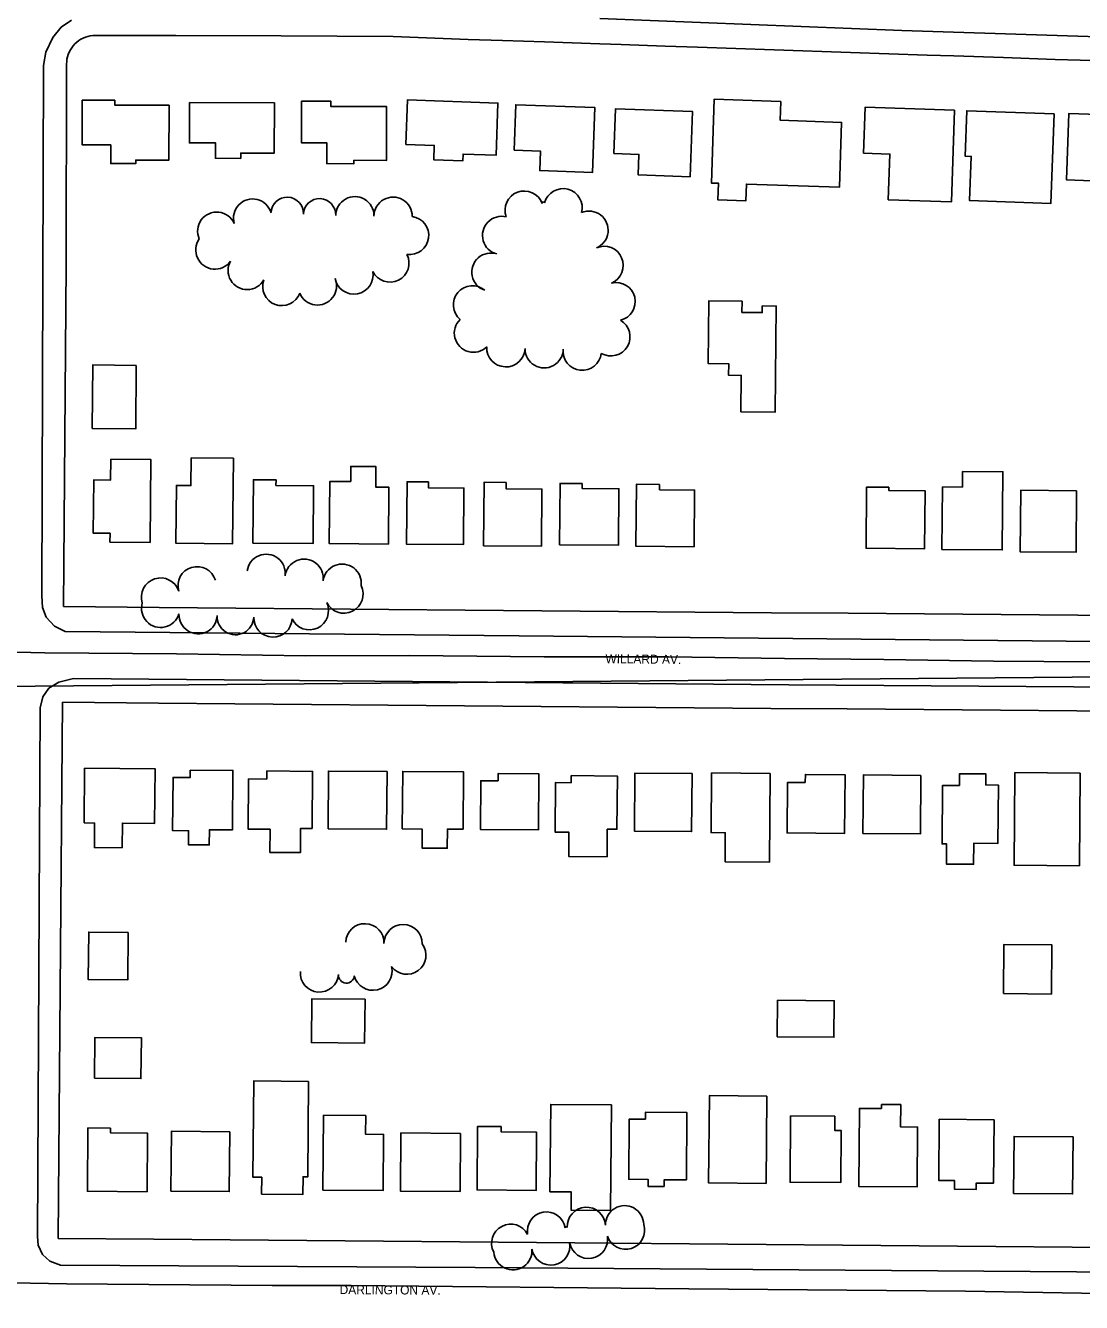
# Model space of a CAD drawing. Extents: x -2233 to 187241, y 4582 to 150524.
# Drawn here: x 113336 to 113887, y 57751 to 58418 of the extents above; entities that cross this region are included whole.
import ezdxf

# ---------------------------------------------------------------- set-up
doc = ezdxf.new("R2010")
doc.units = 0
for name, color, linetype in [('BLDG', 7, 'Continuous'), ('GE_X_CL_2000', 7, 'Continuous'), ('GRID', 7, 'Continuous'), ('ROAD', 7, 'Continuous'), ('ROAD-NAME', 7, 'Continuous'), ('RW_X_Fee_RW', 7, 'Continuous'), ('TREES', 7, 'Continuous')]:
    doc.layers.add(name, color=color, linetype=linetype)

msp = doc.modelspace()

# ---------------------------------------------------------------- linework, layer by layer
at = {"layer": 'BLDG'}
for points in [[(113380.26, 58355.66), (113380.24, 58345.86), (113393.23, 58345.82), (113393.23, 58347.68), (113410.63, 58347.64), (113410.7, 58376.38), (113382.31, 58376.44), (113382.31, 58378.93), (113365.28, 58378.98), (113365.22, 58355.69)], [(113421.35, 58377.7), (113465.72, 58377.59), (113465.66, 58351.32), (113448.15, 58351.37), (113448.14, 58348.58), (113434.94, 58348.61), (113434.96, 58356.64), (113421.29, 58356.67)], [(113479.89, 58378.49), (113495.28, 58378.45), (113495.27, 58375.67), (113524.37, 58375.6), (113524.31, 58347.52), (113507.29, 58347.56), (113507.28, 58345.77), (113493.07, 58345.81), (113493.1, 58356.71), (113479.84, 58356.74)], [(113534.39, 58355.88), (113549.28, 58355.36), (113549.02, 58347.86), (113564.2, 58347.33), (113564.33, 58350.8), (113581.57, 58350.2), (113582.52, 58377.49), (113535.19, 58379.15)], [(113730.4, 58378.37), (113730.05, 58368.51), (113762.14, 58367.39), (113760.96, 58333.49), (113712.34, 58335.18), (113712.03, 58326.32), (113697.52, 58326.83), (113697.82, 58335.54), (113694.05, 58335.67), (113695.58, 58379.59)], [(113591.02, 58352.87), (113604.75, 58352.38), (113604.4, 58342.23), (113631.96, 58341.27), (113633.14, 58375.19), (113591.86, 58376.64)], [(113643.16, 58351.14), (113656.2, 58350.68), (113655.82, 58339.92), (113682.95, 58338.98), (113684.14, 58373.09), (113643.98, 58374.5)], [(113821.14, 58373.76), (113819.47, 58325.8), (113786.5, 58326.95), (113787.34, 58350.85), (113773.59, 58351.33), (113774.43, 58375.4)], [(113873.12, 58371.91), (113871.49, 58324.99), (113829.01, 58326.47), (113829.82, 58349.56), (113826.72, 58349.67), (113827.55, 58373.5)], [(113927.27, 58370.42), (113925.58, 58321.86), (113892.3, 58323.03), (113892.79, 58336.86), (113879.71, 58337.31), (113880.92, 58372.04)], [(113710.11, 58273.89), (113710.06, 58268.1), (113720.61, 58268), (113720.64, 58271.43), (113727.95, 58271.37), (113727.47, 58216), (113709.52, 58216.15), (113709.69, 58235.14), (113703.08, 58235.19), (113703.12, 58241.2), (113692.39, 58241.3), (113692.68, 58274.04)], [(113393.56, 58240.39), (113393.28, 58207.21), (113370.53, 58207.42), (113370.81, 58240.58)], [(113380.21, 58191.35), (113380.12, 58180.44), (113371.29, 58180.51), (113371.05, 58152.68), (113379.85, 58152.6), (113379.81, 58148), (113400.78, 58147.83), (113401.15, 58191.17)], [(113422.21, 58192.06), (113422.09, 58177.53), (113414.49, 58177.6), (113414.22, 58147.4), (113443.91, 58147.15), (113444.29, 58191.87)], [(113505.59, 58179.64), (113505.65, 58187.58), (113518.76, 58187.47), (113518.67, 58176.77), (113525.52, 58176.71), (113525.27, 58146.96), (113494.42, 58147.22), (113494.7, 58179.74)], [(113825.34, 58184.97), (113825.27, 58176.74), (113814.85, 58176.83), (113814.57, 58144.16), (113846.03, 58143.89), (113846.38, 58184.8)], [(113466.54, 58177.62), (113466.56, 58180.48), (113454.77, 58180.59), (113454.49, 58147.48), (113485.93, 58147.21), (113486.19, 58177.46)], [(113546.26, 58179.45), (113546.23, 58176.39), (113564.71, 58176.23), (113564.46, 58146.74), (113534.74, 58146.99), (113535.02, 58179.55)], [(113586.78, 58179.2), (113586.75, 58175.89), (113605.48, 58175.73), (113605.22, 58145.86), (113575.01, 58146.12), (113575.29, 58179.3)], [(113626.61, 58178.56), (113626.59, 58176.02), (113645.74, 58175.86), (113645.49, 58146.36), (113614.72, 58146.62), (113614.99, 58178.66)], [(113666.99, 58178.12), (113666.97, 58175.34), (113685.32, 58175.18), (113685.07, 58145.57), (113654.6, 58145.82), (113654.88, 58178.23)], [(113786.72, 58176.65), (113786.71, 58175.05), (113805.76, 58174.88), (113805.49, 58144.58), (113774.9, 58144.84), (113775.17, 58176.75)], [(113884.91, 58174.87), (113884.64, 58142.73), (113855.41, 58142.98), (113855.69, 58175.12)], [(113366.27, 58001.23), (113371.74, 58001.18), (113371.63, 57988.37), (113386.17, 57988.24), (113386.28, 58001.12), (113403.14, 58000.97), (113403.38, 58029.53), (113366.51, 58029.83)], [(113421.71, 58028.84), (113421.67, 58024.92), (113412.79, 58025.01), (113412.55, 57997.24), (113420.88, 57997.18), (113420.82, 57989.81), (113431.65, 57989.71), (113431.72, 57997.71), (113443.81, 57997.61), (113444.08, 58028.65)], [(113461.78, 58028.41), (113461.74, 58024.12), (113452.19, 58024.21), (113451.97, 57998.05), (113463.5, 57997.95), (113463.39, 57985.87), (113479.3, 57985.73), (113479.41, 57998.39), (113485.39, 57998.33), (113485.65, 58028.2)], [(113493.74, 57998.23), (113524.35, 57997.97), (113524.6, 58028.04), (113493.98, 58028.3)], [(113532.51, 57998.11), (113542.93, 57998.02), (113542.85, 57988.08), (113556.01, 57987.98), (113556.09, 57998.05), (113564.31, 57997.98), (113564.57, 58027.86), (113532.76, 58028.13)], [(113582.63, 58023.19), (113582.67, 58027.11), (113603.89, 58026.94), (113603.64, 57997.56), (113573.35, 57997.82), (113573.57, 58023.27)], [(113620.83, 58025.95), (113620.79, 58022.22), (113612.61, 58022.29), (113612.4, 57996.48), (113619.64, 57996.41), (113619.53, 57983.74), (113639.56, 57983.57), (113639.68, 57997.97), (113644.71, 57997.93), (113644.95, 58025.74)], [(113683.99, 58027.06), (113683.73, 57996.7), (113653.86, 57996.95), (113654.13, 58027.32)], [(113724.87, 58027.13), (113724.48, 57980.77), (113701.19, 57980.96), (113701.33, 57996.15), (113693.88, 57996.22), (113694.14, 58027.39)], [(113743.14, 58022.3), (113743.18, 58026.57), (113763.95, 58026.39), (113763.69, 57995.72), (113733.66, 57995.98), (113733.89, 58022.38)], [(113803.59, 58026.09), (113803.33, 57995.53), (113773.29, 57995.79), (113773.55, 58026.35)], [(113823.67, 58020.75), (113823.73, 58026.94), (113837.5, 58026.82), (113837.45, 58021.1), (113844.03, 58021.05), (113843.77, 57990.54), (113831.16, 57990.65), (113831.07, 57979.63), (113816.85, 57979.75), (113816.94, 57990.23), (113814.65, 57990.25), (113814.9, 58020.83)], [(113886.82, 58027.22), (113886.4, 57978.85), (113852.26, 57979.14), (113852.67, 58027.52)], [(113389.29, 57943.98), (113389.06, 57919.15), (113368.47, 57919.34), (113368.7, 57944.17)], [(113846.71, 57912.01), (113871.75, 57911.78), (113871.99, 57937.49), (113846.95, 57937.72)], [(113513.07, 57909.08), (113512.86, 57886.17), (113485.1, 57886.41), (113485.32, 57909.33)], [(113728.47, 57889.47), (113758.11, 57889.19), (113758.29, 57908.28), (113728.66, 57908.55)], [(113371.75, 57867.86), (113396.01, 57867.64), (113396.21, 57888.92), (113371.94, 57889.15)], [(113483.54, 57866.18), (113483.11, 57816.25), (113480.67, 57816.28), (113480.59, 57807.07), (113459.01, 57807.25), (113459.08, 57816.05), (113454.52, 57816.09), (113454.95, 57866.42)], [(113723.06, 57858.44), (113722.68, 57812.85), (113692.64, 57813.11), (113693.03, 57858.7)], [(113641.88, 57853.85), (113641.41, 57798.72), (113620.76, 57798.9), (113620.85, 57808.38), (113609.72, 57808.48), (113610.1, 57854.12)], [(113659.62, 57846.35), (113659.64, 57850.03), (113681.31, 57849.85), (113681, 57814.65), (113669.4, 57814.75), (113669.37, 57811.22), (113661, 57811.29), (113661.03, 57814.93), (113650.91, 57815.02), (113651.18, 57846.43)], [(113782.99, 57851.96), (113783.01, 57854.07), (113793.06, 57853.99), (113792.95, 57842.34), (113801.85, 57842.26), (113801.58, 57811.02), (113771.06, 57811.29), (113771.4, 57852.06)], [(113513.45, 57848.28), (113513.37, 57838.55), (113522.76, 57838.47), (113522.51, 57809.05), (113491.1, 57809.31), (113491.44, 57848.47)], [(113758.57, 57847.92), (113758.5, 57840.54), (113761.88, 57840.51), (113761.65, 57813.23), (113735.19, 57813.45), (113735.48, 57848.11)], [(113841.79, 57846.09), (113841.51, 57812.97), (113832.51, 57813.04), (113832.48, 57809.71), (113821.13, 57809.81), (113821.17, 57814.3), (113812.85, 57814.37), (113813.13, 57846.33)], [(113380.14, 57841.72), (113380.11, 57839.18), (113399.46, 57839.01), (113399.2, 57808.46), (113367.98, 57808.73), (113368.28, 57841.82)], [(113442.36, 57839.87), (113442.09, 57808.54), (113411.68, 57808.81), (113411.94, 57840.13)], [(113562.98, 57838.95), (113562.71, 57808.55), (113531.6, 57808.82), (113531.86, 57839.22)], [(113584.3, 57842.49), (113584.27, 57839.77), (113602.69, 57839.61), (113602.43, 57809.12), (113571.6, 57809.39), (113571.88, 57842.6)], [(113883.06, 57837.09), (113882.8, 57807.35), (113851.99, 57807.61), (113852.25, 57837.36)]]:
    msp.add_lwpolyline(points, close=True, dxfattribs=at)
at = {"layer": 'GE_X_CL_2000'}
for points in [[(113331.12, 58090.49), (113345.72, 58090.17), (113414.55, 58089.54), (113481.9, 58088.65), (113536.28, 58088.69), (113606.69, 58088.06), (113671.6, 58088.03), (113732.34, 58087.11), (113784.14, 58086.64), (113841.46, 58085.83), (113894.11, 58085.49), (113972.25, 58084.41), (114008.94, 58084.37), (114026.62, 58084.46), (114094.57, 58084.81), (114152.73, 58083.5), (114176.68, 58083.17), (114219.57, 58082.73), (114290.64, 58082.2), (114323.84, 58081.88), (114369.36, 58081.72), (114397.88, 58081.62), (114417.41, 58082.42)], [(113328.71, 57760.92), (113357.14, 57760.34), (113464.47, 57759.44), (113505.75, 57759.44), (113682.24, 57757.66), (113826.93, 57756.54), (113887.41, 57755.4), (114006.38, 57753.93), (114026.62, 57753.91), (114144.9, 57753.95), (114165.26, 57754.04), (114215.74, 57753.2), (114250.99, 57753.06), (114293.63, 57752.51), (114323.99, 57752.37), (114351.5, 57751.49), (114386.06, 57750.91), (114413.46, 57750.61), (114437.69, 57750.71)]]:
    msp.add_lwpolyline(points, dxfattribs=at)
at = {"layer": 'GRID'}
msp.add_line((115008.35, 58087.3), (110008.54, 58043.67), dxfattribs=at)
at = {"layer": 'ROAD'}
for points in [[(113968.86, 58095.42), (113593.66, 58099.06), (113356.37, 58101.34), (113350.75, 58104.11), (113346.53, 58108.85), (113344.56, 58113.75), (113344.11, 58119.97), (113345.08, 58397.18), (113346.26, 58404.13), (113350, 58411.72), (113354.32, 58417.19), (113359.73, 58420.83)], [(113635.86, 58421.69), (113793.66, 58415.46), (113961.25, 58410)], [(114317.24, 57762.87), (113884.78, 57766.54), (113570.69, 57768.95), (113353.92, 57770.13), (113348.35, 57772.16), (113344.55, 57775.7), (113342.27, 57780.47), (113341.91, 57785.02), (113343.31, 58061.48), (113344.71, 58067.11), (113347.9, 58071.73), (113352.99, 58074.89), (113360.68, 58076.68), (113734.57, 58073.33), (114131.51, 58070.69)]]:
    msp.add_lwpolyline(points, dxfattribs=at)
at = {"layer": 'RW_X_Fee_RW'}
for p in [(113357.11, 58397.82), (113355.5, 58114.29)]:
    msp.add_line(p, (113356.99, 58292.6), dxfattribs=at)
for points in [[(113372.13, 58412.8), (113370.82, 58412.74), (113369.53, 58412.57), (113368.25, 58412.29), (113367, 58411.9), (113365.79, 58411.4), (113364.63, 58410.8), (113363.52, 58410.1), (113362.48, 58409.3), (113361.52, 58408.42), (113360.63, 58407.46), (113359.84, 58406.42), (113359.13, 58405.32), (113358.52, 58404.16), (113358.02, 58402.95), (113357.63, 58401.7), (113357.34, 58400.42), (113357.17, 58399.13), (113357.11, 58397.82)], [(113372.13, 58412.8), (113414.18, 58412.74), (113469.18, 58412.66), (113527.77, 58412.34)], [(113669.98, 58407.25), (113646.85, 58408.04), (113635.85, 58408.41), (113606.87, 58409.4), (113584.88, 58410.15), (113566.89, 58410.76), (113527.77, 58412.34)], [(113886.71, 58399.87), (113873.72, 58400.32), (113846.74, 58401.24), (113820.75, 58402.12), (113806.76, 58402.6), (113766.78, 58403.96), (113726.8, 58405.32), (113686.82, 58406.68), (113669.98, 58407.25)], [(113960.19, 58397.37), (113926.69, 58398.51), (113886.71, 58399.87)], [(113355.5, 58114.29), (113405.5, 58113.86), (113445.5, 58113.52), (113485.49, 58113.18), (113525.49, 58112.84), (113565.49, 58112.5), (113605.49, 58112.15), (113645.49, 58111.81), (113685.49, 58111.47), (113725.49, 58111.13), (113765.49, 58110.79), (113805.49, 58110.45), (113845.49, 58110.1), (113885.49, 58109.76)], [(113885.49, 58109.76), (113925.49, 58109.41), (113965.49, 58109.07), (114005.49, 58108.73), (114045.49, 58108.39), (114085.49, 58108.05), (114125.49, 58107.7), (114165.49, 58107.36), (114205.49, 58107.02), (114245.48, 58106.68), (114285.48, 58106.34), (114325.48, 58106), (114390.7, 58105.44)], [(113355.07, 58064.29), (113353.79, 57914.11), (113352.68, 57784.12)], [(113355.07, 58064.29), (113405.07, 58063.87), (113445.07, 58063.52), (113485.07, 58063.18), (113525.07, 58062.84), (113565.07, 58062.5), (113605.07, 58062.16), (113645.07, 58061.81), (113685.07, 58061.47), (113725.07, 58061.13), (113765.07, 58060.79), (113805.07, 58060.45), (113845.07, 58060.11), (113885.07, 58059.76)], [(113885.07, 58059.76), (113925.07, 58059.42), (113965.06, 58059.07), (114005.07, 58058.73), (114045.06, 58058.39), (114085.06, 58058.05), (114125.06, 58057.71), (114165.06, 58057.36), (114205.06, 58057.02), (114245.06, 58056.68), (114285.06, 58056.34), (114325.06, 58056), (114340.06, 58055.87), (114393.73, 58055.41)], [(113882.67, 57779.59), (113842.67, 57779.93), (113802.67, 57780.27), (113762.67, 57780.62), (113722.67, 57780.96), (113682.68, 57781.3), (113642.68, 57781.64), (113602.68, 57781.98), (113562.68, 57782.32), (113522.68, 57782.67), (113482.68, 57783.01), (113442.68, 57783.35), (113402.68, 57783.69), (113352.68, 57784.12)], [(114410.68, 57775.07), (114362.67, 57775.48), (114322.67, 57775.82), (114282.67, 57776.17), (114242.67, 57776.51), (114202.67, 57776.85), (114162.67, 57777.19), (114122.67, 57777.53), (114082.67, 57777.87), (114042.67, 57778.22), (114002.67, 57778.56), (113962.67, 57778.9), (113922.67, 57779.24), (113882.67, 57779.59)]]:
    msp.add_lwpolyline(points, dxfattribs=at)
at = {"layer": 'TREES'}
for centre, radius, start, end in [((113596.23, 58321.52), 10, 20.48545, 200.48545), ((113616.57, 58322.77), 10, 345.17742, 165.17742), ((113454.35, 58317.39), 10, 16.28961, 196.28961), ((113472.41, 58319.83), 8.47, 357.49328, 177.49328), ((113489.31, 58319.09), 8.44, 357.49328, 177.49328), ((113507.74, 58318.59), 10, 359.24476, 179.24476), ((113527.73, 58318.32), 10, 359.24476, 179.24476), ((113606.25, 58325.17), 0.667, 13.64271, 193.64271), ((113435.61, 58310.52), 10, 23.97477, 203.97477), ((113536.37, 58308.28), 10, 262.14477, 82.14477), ((113584.45, 58308.31), 10, 75.99787, 255.99787), ((113630.14, 58311.01), 10, 292.98246, 112.98246), ((113434.62, 58300.66), 10, 144.53142, 324.53142), ((113526.05, 58293.91), 10, 206.54606, 26.54606), ((113578.85, 58289.13), 10, 71.47309, 251.47309), ((113638, 58292.62), 10, 293.29543, 113.29543), ((113451.49, 58289.97), 10, 150.76789, 330.76789), ((113469.59, 58281.6), 10, 159.60159, 339.60159), ((113488.21, 58281.93), 10, 202.384, 22.384), ((113507.28, 58287.59), 10, 190.67888, 10.67888), ((113644.26, 58273.7), 10, 283.36344, 103.36344), ((113569.22, 58272.01), 10, 49.77795, 229.77795), ((113569.73, 58257.21), 10, 134.189, 314.189), ((113641.56, 58255.32), 10, 239.92452, 59.92452), ((113586.69, 58249.58), 10, 177.39829, 357.39829), ((113606.68, 58249.02), 10, 179.36909, 359.36909), ((113626.61, 58247.79), 10, 173.56549, 353.56549), ((113461.43, 58131.68), 10, 352.61561, 172.61561), ((113481.26, 58129.11), 10, 352.61561, 172.61561), ((113425.32, 58125.2), 10, 16.50903, 196.50903), ((113501.1, 58126.54), 10, 352.61561, 172.61561), ((113406.21, 58119.3), 10, 17.82319, 197.82319), ((113502.04, 58120.83), 10, 206.2314, 26.2314), ((113406.28, 58113.38), 10, 163.40104, 343.40104), ((113425.85, 58110.07), 10, 177.39954, 357.39954), ((113484.02, 58112.17), 10, 205.07469, 25.07469), ((113445.41, 58109.18), 9.58, 177.39954, 357.39954), ((113464.97, 58108.34), 10, 177.6734, 357.6734), ((113512.99, 57938.58), 10, 358.19911, 178.19911), ((113532.98, 57938.16), 10, 359.40246, 179.40246), ((113534.94, 57932.11), 10, 216.49219, 36.49219), ((113489.25, 57922.81), 10, 175.43786, 355.43786), ((113517.19, 57923.76), 10, 193.88527, 13.88527), ((113503.35, 57921.69), 4.15, 175.43786, 355.43786), ((113607.89, 57787.93), 10, 9.85604, 189.85604), ((113628.76, 57790.38), 10, 3.41911, 183.41911), ((113648.74, 57791.21), 10, 1.30579, 181.30579), ((113589.2, 57781.54), 10, 27.88027, 207.88027), ((113618.26, 57789.71), 0.525, 7.9674, 187.9674), ((113649.22, 57788.37), 10, 197.86055, 17.86055), ((113629.85, 57783.59), 10, 189.86755, 9.86755), ((113590.33, 57777.65), 10, 184.53426, 4.53426), ((113610.15, 57780.16), 10, 189.86755, 9.86755)]:
    msp.add_arc(centre, radius, start, end, dxfattribs=at)

# ---------------------------------------------------------------- texts
at = {"layer": 'ROAD-NAME'}
for s, rotation, p in [('WILLARD AV.', 359.44817, (113638.68, 58084.72)), ('DARLINGTON AV.', 359.65043, (113499.77, 57754.99))]:
    msp.add_text(s, height=4.68, rotation=rotation, dxfattribs=at).set_placement(p)

doc.saveas('drawing.dxf')
